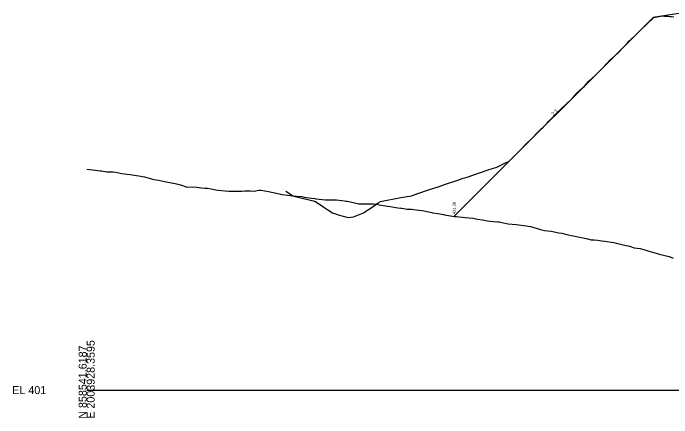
# Model space of a CAD drawing. Extents: x 2004049 to 2067449, y 841632 to 859611.
# Drawn here: x 2061920.8 to 2062151, y 844203.8 to 844345.4 of the extents above; entities that cross this region are included whole.
import ezdxf

# ---------------------------------------------------------------- set-up
doc = ezdxf.new("R2010")
doc.units = 0
for name, color, linetype in [('RD_DDB_Profile_Elev', 7, 'Continuous'), ('RD_GPK_XS_Cell', 7, 'Continuous'), ('RD_XS_EarthShd', 7, 'Continuous'), ('RD_XS_EwShp1', 7, 'Continuous'), ('RD_XS_ExGround', 7, 'Continuous'), ('RD_XS_TieSlope', 7, 'Continuous'), ('RD_XS_TX_Ditch', 7, 'Continuous'), ('RD_XS_TX_Slope', 7, 'Continuous')]:
    doc.layers.add(name, color=color, linetype=linetype)

msp = doc.modelspace()

# ---------------------------------------------------------------- linework, layer by layer
at = {"layer": 'RD_DDB_Profile_Elev'}
msp.add_lwpolyline([(2062016.1, 844283.07), (2062017.7, 844282.01), (2062018.06, 844281.77), (2062018.42, 844281.53), (2062025.24, 844279.82), (2062026.43, 844279.53), (2062026.91, 844279.2), (2062027.54, 844278.79), (2062029.43, 844277.53), (2062030.83, 844276.59), (2062032.42, 844275.53), (2062033.16, 844275.28), (2062033.88, 844275.04), (2062034.38, 844274.87), (2062037.94, 844273.89), (2062039.74, 844274.15), (2062042.71, 844275.32), (2062043.24, 844275.53), (2062045.33, 844276.92), (2062046.24, 844277.53), (2062048.44, 844278.99), (2062049.24, 844279.53), (2062056.35, 844280.84), (2062060.09, 844281.53), (2062062.22, 844282.24), (2062066.02, 844283.53), (2062069.66, 844284.75), (2062071.96, 844285.53), (2062076.25, 844286.97), (2062078.12, 844287.61), (2062079.47, 844288.06), (2062083.86, 844289.53), (2062086.88, 844290.54), (2062089.84, 844291.53), (2062092.69, 844292.92), (2062094.15, 844293.57), (2062096.37, 844295.76), (2062098.19, 844297.59), (2062099.96, 844299.53), (2062102.24, 844301.64), (2062103.98, 844303.53), (2062105.12, 844304.66), (2062106, 844305.53), (2062107.41, 844306.9), (2062108.06, 844307.53), (2062108.66, 844308.15), (2062110, 844309.53), (2062111.22, 844310.75), (2062112, 844311.53), (2062112.59, 844312.09), (2062114.34, 844313.72), (2062115.88, 844315.22), (2062116.29, 844315.63), (2062117.99, 844317.53), (2062118.8, 844318.26), (2062120.39, 844319.74), (2062121.98, 844321.53), (2062124.2, 844323.53), (2062124.59, 844323.93), (2062126.16, 844325.53), (2062127.67, 844327.07), (2062128.11, 844327.53), (2062129.63, 844329.12), (2062130.02, 844329.53), (2062132.23, 844331.53), (2062134.24, 844333.53), (2062135.65, 844335.09), (2062136.05, 844335.53), (2062136.61, 844336.05), (2062138.22, 844337.53), (2062139.6, 844338.9), (2062140.23, 844339.53), (2062142.24, 844341.53), (2062144.89, 844343.91), (2062145.29, 844344), (2062145.63, 844344.06), (2062146, 844344.13), (2062146.35, 844344.2), (2062147.99, 844344.39), (2062148.44, 844344.35), (2062149.01, 844344.31), (2062149.66, 844344.25), (2062150.34, 844344.2), (2062150.95, 844344.15), (2062151.74, 844344.09)], dxfattribs=at)
at = {"layer": 'RD_GPK_XS_Cell'}
msp.add_line((2061946.51, 844213.53), (2062196.51, 844213.53), dxfattribs=at)
at = {"layer": 'RD_XS_EarthShd'}
msp.add_line((2062154.28, 844345.36), (2062148.27, 844344.4), dxfattribs=at)
at = {"layer": 'RD_XS_EwShp1'}
for p, q in [((2062154.28, 844345.36), (2062148.27, 844344.4)), ((2062144.52, 844343.8), (2062074.95, 844274.31)), ((2062148.27, 844344.4), (2062144.52, 844343.8))]:
    msp.add_line(p, q, dxfattribs=at)
at = {"layer": 'RD_XS_ExGround'}
msp.add_lwpolyline([(2061946.51, 844290.84), (2061947.45, 844290.72), (2061949.64, 844290.47), (2061951.2, 844290.27), (2061951.72, 844290.24), (2061953.57, 844289.89), (2061954.96, 844289.9), (2061955.71, 844289.87), (2061956.72, 844289.71), (2061958.71, 844289.3), (2061961.71, 844288.91), (2061962.46, 844288.82), (2061964.73, 844288.47), (2061966.71, 844288.11), (2061969.97, 844287.24), (2061971.7, 844286.92), (2061973.72, 844286.44), (2061976.7, 844285.88), (2061977.48, 844285.77), (2061979.29, 844285.34), (2061981.23, 844284.68), (2061981.69, 844284.61), (2061984.98, 844284.48), (2061986.69, 844284.28), (2061987.86, 844284.21), (2061988.74, 844284.13), (2061990, 844283.96), (2061991.68, 844283.62), (2061992.49, 844283.48), (2061994.92, 844283.26), (2061996.24, 844283.13), (2061996.68, 844283.1), (2061999.99, 844283.07), (2062000.72, 844283.09), (2062001.68, 844283.19), (2062002.86, 844283.22), (2062003.75, 844283.2), (2062005, 844283.07), (2062006.67, 844283.41), (2062007.5, 844283.41), (2062010.01, 844282.96), (2062011.67, 844282.63), (2062015.01, 844281.99), (2062016.66, 844281.66), (2062018.76, 844281.42), (2062020, 844281.38), (2062021.66, 844281.2), (2062022.51, 844281.06), (2062025.1, 844280.69), (2062026.27, 844280.53), (2062026.65, 844280.48), (2062030.02, 844280.11), (2062030.72, 844280.12), (2062031.65, 844280.09), (2062033.77, 844280.03), (2062036.64, 844279.72), (2062037.15, 844279.66), (2062037.53, 844279.58), (2062040.2, 844278.98), (2062041.64, 844278.72), (2062045.03, 844278.68), (2062046.63, 844278.62), (2062047.86, 844278.61), (2062048.79, 844278.3), (2062051.63, 844277.84), (2062052.54, 844277.77), (2062055.29, 844277.33), (2062056.29, 844277.18), (2062056.62, 844277.13), (2062058.58, 844276.83), (2062060.04, 844276.85), (2062061.62, 844276.63), (2062063.8, 844276.31), (2062066.61, 844275.79), (2062067.15, 844275.66), (2062067.55, 844275.53), (2062069.29, 844275.24), (2062071.3, 844274.92), (2062071.61, 844274.85), (2062075.06, 844274.29), (2062075.72, 844274.23), (2062076.6, 844274.14), (2062077.86, 844273.99), (2062078.81, 844273.86), (2062081.6, 844273.62), (2062082.56, 844273.48), (2062085.48, 844272.97), (2062086.59, 844272.77), (2062088.58, 844272.55), (2062090.07, 844272.4), (2062090.72, 844272.34), (2062091.59, 844272.13), (2062093.82, 844271.71), (2062096.58, 844271.46), (2062097.58, 844271.35), (2062099.29, 844271.12), (2062101.58, 844270.72), (2062105.08, 844269.67), (2062106.57, 844269.39), (2062108.83, 844269.07), (2062111.57, 844268.53), (2062112.59, 844268.36), (2062114.29, 844267.99), (2062116.56, 844267.47), (2062120.09, 844266.81), (2062121.56, 844266.44), (2062122.87, 844266.13), (2062123.85, 844266.04), (2062125.01, 844265.99), (2062126.55, 844265.78), (2062127.6, 844265.62), (2062130.76, 844265.1), (2062131.55, 844264.97), (2062135.11, 844264.15), (2062135.72, 844264.01), (2062136.55, 844263.71), (2062137.87, 844263.27), (2062138.86, 844263.14), (2062140.01, 844263.03), (2062141.54, 844262.58), (2062142.61, 844262.2), (2062145.85, 844261.32), (2062146.54, 844261.13), (2062148.58, 844260.6), (2062150.12, 844260.24), (2062151.53, 844259.67)], dxfattribs=at)
at = {"layer": 'RD_XS_TieSlope'}
for p, q in [((2062144.52, 844343.8), (2062074.95, 844274.31)), ((2062148.27, 844344.4), (2062144.52, 844343.8))]:
    msp.add_line(p, q, dxfattribs=at)

# ---------------------------------------------------------------- texts
at = {"layer": 'RD_GPK_XS_Cell'}
for s, p in [('E 2003928.3595', (2061949.31, 844203.53)), ('N 858541.6187', (2061946.51, 844203.53))]:
    msp.add_text(s, height=2.8, rotation=90, dxfattribs=at).set_placement(p)
msp.add_text('EL 401', height=2.8, dxfattribs=at).set_placement((2061920.51, 844212.13))
at = {"layer": 'RD_XS_TX_Ditch'}
msp.add_text('431.39', height=1, rotation=90, dxfattribs=at).set_placement((2062075.45, 844275.11))
at = {"layer": 'RD_XS_TX_Slope'}
msp.add_text('2:1', height=1.25, rotation=44.971, dxfattribs=at).set_placement((2062109.65, 844309.41))

doc.saveas('drawing.dxf')
